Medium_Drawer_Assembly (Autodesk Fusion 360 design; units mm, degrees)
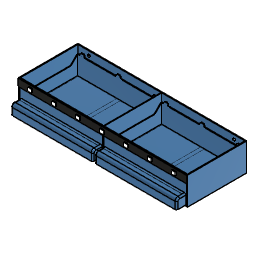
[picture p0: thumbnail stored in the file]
sketch "Bottom" plane through (0, 0, 0) normal (0, 0, 1) x axis (1, 0, 0)
  line L1 (232.6, 0) -> (0, 0)
  line L2 (232.6, 81.6) -> (232.6, 0)
  line L3 (0, 81.6) -> (232.6, 81.6)
  line L4 (0, 0) -> (0, 81.6)
  line L5 (231.4, 80.4) -> (1.2, 80.4)
  line L6 (231.4, 1.2) -> (231.4, 80.4)
  line L7 (1.2, 1.2) -> (231.4, 1.2)
  line L8 (1.2, 80.4) -> (1.2, 1.2)
  line L9 (3.2, 78.4) -> (3.2, 3.2)
  line L10 (34.2, 80.4) -> (33.4, 80.4)
  line L11 (33.4, 1.2) -> (34.2, 1.2)
  line L12 (67.2, 80.4) -> (66.4, 80.4)
  line L13 (66.4, 1.2) -> (67.2, 1.2)
  line L14 (100.2, 80.4) -> (99.4, 80.4)
  line L15 (99.4, 1.2032) -> (100.2, 1.2032)
  line L16 (133.2, 80.4) -> (132.4, 80.4)
  line L17 (132.4, 1.2) -> (133.2, 1.2)
  line L18 (166.2, 80.4) -> (165.4, 80.4)
  line L19 (165.4, 1.2) -> (166.2, 1.2)
  line L20 (199.2, 80.4) -> (198.4, 80.4)
  line L21 (198.4, 1.2) -> (199.2, 1.2)
  line L22 (229.4, 3.2) -> (229.4, 78.4)
  line L23 (232.2, 80.4) -> (231.4, 80.4)
  line L24 (231.4, 1.2) -> (232.2, 1.2)
  line L25 (115.9, 3.2) -> (115.9, 78.4)
  line L26 (116.7, 3.2) -> (116.7, 78.4)
  line L27 (116.7, 80.4) -> (116.7, 78.4)
  line L28 (115.9, 80.4) -> (115.9, 78.4)
  line L29 (116.7, 1.2) -> (116.7, 3.2)
  line L30 (115.9, 1.2) -> (115.9, 3.2)
  line L31 (113.9, 3.2) -> (113.9, 78.4)
  line L32 (113.9, 78.4) -> (3.2, 78.4)
  line L33 (3.2, 3.2) -> (113.9, 3.2)
  line L34 (118.7, 78.4) -> (229.4, 78.4)
  line L35 (118.7, 3.2) -> (118.7, 78.4)
  line L36 (118.7, 3.2) -> (229.4, 3.2)
  line L37 (56.2, 3.2) -> (56.2, 78.4)
  line L38 (61.2, 3.2) -> (61.2, 78.4)
  line L39 (171.7, 3.2) -> (171.7, 78.4)
  line L40 (176.7, 78.4) -> (176.7, 3.2)
  point P1 (0, 0)
  point P2 (0, 0)
  point P14 (34.2, 1.2)
  point P12 (33.4, 80.4)
  point P16 (66.4, 80.4)
  point P20 (99.4, 80.4)
  point P24 (132.4, 80.4)
  point P28 (165.4, 80.4)
  point P32 (198.4, 80.4)
  point P38 (231.4, 80.4)
  point P46 (116.7, 80.4)
  point P47 (115.9, 80.4)
  point P48 (116.7, 1.2)
  point P49 (115.9, 1.2)
  point P54 (56.2, 78.4)
  point P55 (56.2, 3.2)
  point P56 (61.2, 78.4)
  point P57 (61.2, 3.2)
  point P58 (171.7, 78.4)
  point P59 (171.7, 3.2)
  point P60 (176.7, 3.2)
  point P61 (176.7, 78.4)
  point P5 (0, 81.6)
  horizontal L1
  vertical L2
  horizontal L3
  vertical L4
  coincident P1 P2
  horizontal L5
  vertical L6
  horizontal L7
  vertical L8
  vertical L9
  horizontal L10
  coincident L7 P14
  coincident L5 P12
  horizontal L12
  horizontal L13
  coincident L5 P16
  horizontal L14
  horizontal L15
  coincident L5 P20
  horizontal L16
  horizontal L17
  coincident L5 P24
  horizontal L18
  horizontal L19
  coincident L5 P28
  horizontal L20
  horizontal L21
  coincident L5 P32
  vertical L22
  horizontal L23
  horizontal L24
  coincident L5 P38
  coincident L5 P46
  perpendicular L5 L27
  coincident L5 P47
  perpendicular L5 L28
  coincident L7 P48
  perpendicular L7 L29
  coincident L7 P49
  perpendicular L7 L30
  perpendicular L31 L32
  perpendicular L9 L33
  perpendicular L25 L34
  perpendicular L35 L36
  coincident L32 P54
  coincident L33 P55
  perpendicular L33 L37
  coincident L32 P56
  coincident L33 P57
  perpendicular L33 L38
  coincident L34 P58
  coincident L36 P59
  perpendicular L36 L39
  coincident L36 P60
  coincident L34 P61
  perpendicular L34 L40
  dimension "d1_3" distance L4 L8 = 1.2
  dimension "d2_3" distance L3 L5 = 1.2
  dimension "d3_3" distance L1 L7 = 1.2
  dimension "d4_3" distance L2 L6 = 1.2
  dimension "d5_3" distance L8 L9 = 2
  dimension "d8_1" distance P2 P5 = 81.6
  dimension "d52_2" distance L6 L22 = 2
  dimension "d173" distance L9 L25 = 112.7 (= "( ( 226.2 / 2 ) * 1 mm ) - 0.4 mm")
  dimension "d174" distance L22 L26 = 112.7 (= "( ( 226.2 / 2 ) * 1 mm ) - 0.4 mm")
  dimension "d175" distance L25 L26 = 0.8
  dimension "d190" distance L25 L31 = 2
  dimension "d191" distance L5 L32 = 2
  dimension "d192" distance L7 L33 = 2
  dimension "d193" distance L26 L35 = 2
  dimension "d194" distance L7 L36 = 2
  dimension "d195" distance L5 L34 = 2
  dimension "d203" distance L37 L38 = 5
  dimension "d204" distance L9 L37 = 53
  dimension "d206" distance L39 L40 = 5
  dimension "d207" distance L35 L39 = 53
extrude "Extrude2" new body sketch "Bottom" profile of L1 L2 L3 L4 L5 L6 L7 L8 L10 L11 L12 L13 L14 L16 L17 L18 L19 L20 L21 L25 L26 L27 L28 L29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 along normal blind 38.2 named "d57_2"
sketch "Front" plane through (0, 0, 0) normal (0, -1, 0) x axis (1, 0, 0)
  line L1 (232.6, 0) -> (0, 0)
  line L2 (232.6, 38.2) -> (232.6, 0)
  line L3 (0, 38.2) -> (232.6, 38.2)
  line L4 (0, 0) -> (0, 38.2)
  line L5 (33.4, 28.2) -> (1.2, 28.2)
  line L6 (1.2, 1.2) -> (33.4, 1.2)
  line L7 (1.2, 28.2) -> (1.2, 1.2)
  line L8 (1.2, 38.2) -> (1.2, 0)
  line L9 (231.4, 1.2) -> (231.4, 28.2)
  line L10 (231.4, 28.2) -> (33.4, 28.2)
  line L11 (33.4, 1.2) -> (231.4, 1.2)
  point P6 (1.2, 28.2)
  point P9 (1.2, 1.2)
  point P12 (231.4, 28.2)
  point P13 (231.4, 1.2)
  horizontal L5
  horizontal L6
  vertical L7
  collinear L7 L8
  vertical L9
  perpendicular L9 L10
  dimension "d80" distance P6 P9 = 27
  dimension "d83" distance L3 L5 = 10
  dimension "d91" distance P12 P13 = 27
  dimension "d294" distance L2 L9 = 1.2
sketch "Back" plane through (0, 80.4, 0) normal (0, -1, 0) x axis (1, 0, 0)
  line L1 (231.4, 38.2) -> (231.4, 0)
  line L2 (1.2, 38.2) -> (115.9, 38.2)
  line L3 (1.2, 0) -> (1.2, 38.2)
  line L4 (3.2, 7) -> (3.2, 23)
  line L5 (115.9, 38.2) -> (115.9, 0)
  line L6 (116.7, 0) -> (116.7, 38.2)
  line L7 (116.7, 38.2) -> (231.4, 38.2)
  line L8 (231.4, 0) -> (116.7, 0)
  line L9 (115.9, 0) -> (1.2, 0)
  line L10 (6.7355, 26.5355) -> (3.2, 23)
  line L11 (8.2, 23) -> (3.2, 23)
  line L12 (31.7355, 26.5355) -> (6.7355, 26.5355)
  line L13 (35.2711, 23) -> (31.7355, 26.5355)
  line L14 (36.7355, 26.5355) -> (31.7355, 26.5355)
  line L15 (35.2711, 7) -> (35.2711, 23)
  line L16 (31.7355, 3.4645) -> (35.2711, 7)
  line L17 (6.7355, 3.4645) -> (3.2, 7)
  line L18 (8.2, 7) -> (3.2, 7)
  line L19 (31.7355, 3.4645) -> (6.7355, 3.4645)
  line L20 (68.6066, 26.5355) -> (43.6066, 26.5355)
  line L21 (43.6066, 26.5355) -> (40.0711, 23)
  line L22 (40.0711, 7) -> (40.0711, 23)
  line L23 (43.6066, 3.4645) -> (40.0711, 7)
  line L24 (68.6066, 3.4645) -> (43.6066, 3.4645)
  line L25 (68.6066, 3.4645) -> (72.1421, 7)
  line L26 (72.1421, 7) -> (72.1421, 23)
  line L27 (72.1421, 23) -> (68.6066, 26.5355)
  line L28 (105.4777, 26.5355) -> (80.4777, 26.5355)
  line L29 (80.4777, 26.5355) -> (76.9421, 23)
  line L30 (76.9421, 7) -> (76.9421, 23)
  line L31 (80.4777, 3.4645) -> (76.9421, 7)
  line L32 (105.4777, 3.4645) -> (80.4777, 3.4645)
  line L33 (105.4777, 3.4645) -> (109.0132, 7)
  line L34 (109.0132, 7) -> (109.0132, 23)
  line L35 (109.0132, 23) -> (105.4777, 26.5355)
  line L36 (152.1223, 26.5355) -> (127.1223, 26.5355)
  line L37 (127.1223, 26.5355) -> (123.5868, 23)
  line L38 (123.5868, 7) -> (123.5868, 23)
  line L39 (127.1223, 3.4645) -> (123.5868, 7)
  line L40 (152.1223, 3.4645) -> (127.1223, 3.4645)
  line L41 (152.1223, 3.4645) -> (155.6579, 7)
  line L42 (155.6579, 7) -> (155.6579, 23)
  line L43 (155.6579, 23) -> (152.1223, 26.5355)
  line L44 (188.9934, 26.5355) -> (163.9934, 26.5355)
  line L45 (163.9934, 26.5355) -> (160.4579, 23)
  line L46 (160.4579, 7) -> (160.4579, 23)
  line L47 (163.9934, 3.4645) -> (160.4579, 7)
  line L48 (188.9934, 3.4645) -> (163.9934, 3.4645)
  line L49 (188.9934, 3.4645) -> (192.5289, 7)
  line L50 (192.5289, 7) -> (192.5289, 23)
  line L51 (192.5289, 23) -> (188.9934, 26.5355)
  line L52 (225.8645, 26.5355) -> (200.8645, 26.5355)
  line L53 (200.8645, 26.5355) -> (197.3289, 23)
  line L54 (197.3289, 7) -> (197.3289, 23)
  line L55 (200.8645, 3.4645) -> (197.3289, 7)
  line L56 (225.8645, 3.4645) -> (200.8645, 3.4645)
  line L57 (225.8645, 3.4645) -> (229.4, 7)
  line L58 (229.4, 7) -> (229.4, 23)
  line L59 (229.4, 23) -> (225.8645, 26.5355)
  line L60 (232.6, 38.2) -> (232.6, 0)
  point P5 (3.2, 7)
  point P6 (3.2, 23)
  point P12 (6.7355, 26.5355)
  point P14 (31.7355, 26.5355)
  point P15 (35.2711, 23)
  point P17 (35.2711, 7)
  point P18 (31.7355, 3.4645)
  point P19 (6.7355, 3.4645)
  point P23 (40.0711, 23)
  point P26 (40.0711, 7)
  point P21 (43.6066, 26.5355)
  point P28 (68.6066, 26.5355)
  point P27 (72.1421, 23)
  point P22 (68.6066, 3.4645)
  point P25 (72.1421, 7)
  point P24 (43.6066, 3.4645)
  point P31 (76.9421, 23)
  point P34 (76.9421, 7)
  point P29 (80.4777, 26.5355)
  point P36 (105.4777, 26.5355)
  point P35 (109.0132, 23)
  point P30 (105.4777, 3.4645)
  point P33 (109.0132, 7)
  point P32 (80.4777, 3.4645)
  point P39 (123.5868, 23)
  point P42 (123.5868, 7)
  point P37 (127.1223, 26.5355)
  point P44 (152.1223, 26.5355)
  point P43 (155.6579, 23)
  point P38 (152.1223, 3.4645)
  point P41 (155.6579, 7)
  point P40 (127.1223, 3.4645)
  point P47 (160.4579, 23)
  point P50 (160.4579, 7)
  point P45 (163.9934, 26.5355)
  point P52 (188.9934, 26.5355)
  point P51 (192.5289, 23)
  point P46 (188.9934, 3.4645)
  point P49 (192.5289, 7)
  point P48 (163.9934, 3.4645)
  point P55 (197.3289, 23)
  point P58 (197.3289, 7)
  point P53 (200.8645, 26.5355)
  point P60 (225.8645, 26.5355)
  point P59 (229.4, 23)
  point P54 (225.8645, 3.4645)
  point P57 (229.4, 7)
  point P56 (200.8645, 3.4645)
  parallel L3 L4
  horizontal L11
  horizontal L12
  horizontal L14
  vertical L15
  horizontal L18
  horizontal L20
  vertical L26
  horizontal L28
  vertical L34
  horizontal L36
  vertical L42
  horizontal L44
  vertical L50
  horizontal L52
  vertical L58
  dimension "d102" distance L3 L4 = 2
  dimension "d211" distance P5 P6 = 16
  dimension "d214" distance P5 L9 = 7
  dimension "d216" distance P6 P12 = 5
  dimension "d217" angle L10 L11 = 45
  dimension "d218" distance P12 P14 = 25
  dimension "d219" angle L13 L14 = 45
  dimension "d220" distance P14 P15 = 5
  dimension "d221" angle L15 L16 = 135
  dimension "d222" distance P17 P18 = 5
  dimension "d223" angle L17 L18 = 45
  dimension "d224" distance P5 P19 = 5
  dimension "d225" distance P23 P26 = 16
  dimension "d226" distance P21 P23 = 5
  dimension "d227" distance P21 P28 = 25
  dimension "d228" distance P27 P28 = 5
  dimension "d229" angle L25 L26 = 135
  dimension "d230" distance P22 P25 = 5
  dimension "d231" distance P24 P26 = 5
  dimension "d232" distance P31 P34 = 16
  dimension "d233" distance P29 P31 = 5
  dimension "d234" distance P29 P36 = 25
  dimension "d235" distance P35 P36 = 5
  dimension "d236" angle L33 L34 = 135
  dimension "d237" distance P30 P33 = 5
  dimension "d238" distance P32 P34 = 5
  dimension "d239" distance P39 P42 = 16
  dimension "d240" distance P37 P39 = 5
  dimension "d241" distance P37 P44 = 25
  dimension "d242" distance P43 P44 = 5
  dimension "d243" angle L41 L42 = 135
  dimension "d244" distance P38 P41 = 5
  dimension "d245" distance P40 P42 = 5
  dimension "d246" distance P47 P50 = 16
  dimension "d247" distance P45 P47 = 5
  dimension "d248" distance P45 P52 = 25
  dimension "d249" distance P51 P52 = 5
  dimension "d250" angle L49 L50 = 135
  dimension "d251" distance P46 P49 = 5
  dimension "d252" distance P48 P50 = 5
  dimension "d253" distance P55 P58 = 16
  dimension "d254" distance P53 P55 = 5
  dimension "d255" distance P53 P60 = 25
  dimension "d256" distance P59 P60 = 5
  dimension "d257" angle L57 L58 = 135
  dimension "d258" distance P54 P57 = 5
  dimension "d259" distance P56 P58 = 5
  dimension "d260" distance L15 L22 = 4.8
  dimension "d261" distance L26 L30 = 4.8
  dimension "d262" distance L50 L54 = 4.8
  dimension "d263" distance L42 L46 = 4.8
  dimension "d264" distance L36 L40 = 23.0711
  dimension "d265" distance L8 L40 = 3.4645
  dimension "d266" distance L38 L42 = 32.0711
  dimension "d267" distance L8 L48 = 3.4645
  dimension "d268" distance L58 L60 = 3.2
  dimension "d269" distance L6 L38 = 6.8868
  dimension "d270" angle L44 L45 = 135
  dimension "d272" angle L44 L51 = 135
  dimension "d273" distance L44 L48 = 23.0711
  dimension "d274" angle L52 L53 = 135
  dimension "d275" distance L52 L56 = 23.0711
  dimension "d279" angle L36 L37 = 135
  dimension "d280" distance L28 L32 = 23.0711
  dimension "d281" angle L28 L35 = 135
  dimension "d283" distance L30 L34 = 32.0711
  dimension "d284" distance L22 L26 = 32.0711
  dimension "d285" angle L20 L21 = 135
  dimension "d286" angle L20 L27 = 135
  dimension "d287" distance L20 L24 = 23.0711
  dimension "d288" angle L21 L22 = 135
  dimension "d290" distance L9 L24 = 3.4645
  dimension "d292" angle L16 L19 = 135
  dimension "d297" distance L9 L32 = 3.4645
  dimension "d298" distance L8 L56 = 3.4645
sketch "Mounting" plane through (0, 80.4, 0) normal (0, -1, 0) x axis (1, 0, 0)
  line L1 (231.4, 38.2) -> (231.4, 0)
  line L2 (1.2, 38.2) -> (115.9, 38.2)
  line L3 (1.2, 0) -> (1.2, 38.2)
  line L4 (115.9, 38.2) -> (115.9, 0)
  line L5 (116.7, 0) -> (116.7, 38.2)
  line L6 (116.7, 38.2) -> (231.4, 38.2)
  line L7 (231.4, 0) -> (116.7, 0)
  line L8 (115.9, 0) -> (1.2, 0)
  circle C1 centre (216.3, 32.2) radius 2
  circle C2 centre (16.3, 32.2) radius 2
  point P6 (16.3, 32.2)
  point P5 (216.3, 32.2)
  dimension "d165" diameter C1 = 4
  dimension "d166" diameter C2 = 4
  dimension "d167" distance L3 P6 = 15.1
  dimension "d168" distance L2 P6 = 6
  dimension "d169" distance L1 P5 = 15.1
  dimension "d170" distance L2 P5 = 6
extrude "Extrude9" cut sketch "Front" profile of L5 L6 L7 L8 L9 L10 L11 to an object
extrude "Extrude10" cut sketch "Back" profile of L4 L10 L12 L13 L15 L16 L17 L19 L20 L21 L22 L23 L24 L25 L26 L27 L28 L29 L30 L31 L32 L33 L34 L35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 against normal blind 1.2
extrude "Extrude11" cut sketch "Mounting" profile of C1 C2 against normal blind 1.2
extrude "Extrude12" add sketch "Bottom" profile of L5 L7 L8 L9 L10 L11 L12 L13 L14 L28 L30 to an object
extrude "Extrude13" add sketch "Bottom" profile of L5 L6 L7 L16 L17 L18 L19 L20 L21 L22 L26 L27 L29 L32 L33 L34 L35 L36 L37 L38 to an object
extrude "Extrude14" add of existing geometry to an object
extrude "Extrude15" add sketch "Bottom" profile of L34 L36 L39 L40 along normal blind 1.2
sketch "Sketch1" plane through (0, 0, 0) normal (0, 0, 1) x axis (1, 0, 0)
  line L1 (113.9, 0) -> (0, 0)
  line L2 (113.9, 80) -> (113.9, 0)
  line L3 (0, 80) -> (113.9, 80)
  line L4 (0, 0) -> (0, 80)
  point P1 (0, 0)
  point P2 (0, 0)
  point P3 (113.9, 0)
  point P4 (113.9, 80)
  horizontal L1
  vertical L2
  horizontal L3
  vertical L4
  coincident P1 P2
  dimension "d1_1" distance P2 P3 = 113.9 (= "114.7 mm - 0.8 mm")
  dimension "d2_1" distance P3 P4 = 80
extrude "Extrude1" new body sketch "Sketch1" along normal blind 26.2 named "d3_1"
shell "Shell1" innerThickness 0.8 named "d5_1"
work_plane "WorkPlane1" AlongDistance -18.4 named "d6_1"
sketch "Sketch3" plane through (0, 80, 0) normal (0, 1, 0) x axis (-1, 0, 0)
  line L1 (0, 0) -> (-113.9, 0)
  line L2 (0, 26.2) -> (0, 0)
  line L3 (-113.9, 26.2) -> (0, 26.2)
  line L4 (-113.9, 0) -> (-113.9, 26.2)
  line L5 (-56.95, 0) -> (-56.95, 26.2)
  line L6 (-109.65, 28.45) -> (-109.65, 27.45)
  line L7 (-105.4, 29.7) -> (-108.4, 29.7)
  line L8 (-104.15, 27.45) -> (-104.15, 28.45)
  line L9 (-102.9, 26.2) -> (-110.9, 26.2)
  line L10 (-8.5, 29.7) -> (-5.5, 29.7)
  line L11 (-4.25, 28.45) -> (-4.25, 27.45)
  line L12 (-11, 26.2) -> (-3, 26.2)
  line L13 (-9.75, 27.45) -> (-9.75, 28.45)
  line L14 (-55.25, 29.7) -> (-58.25, 29.7)
  line L15 (-59.5, 28.45) -> (-59.5, 27.45)
  line L16 (-52.75, 26.2) -> (-60.75, 26.2)
  line L17 (-54, 27.45) -> (-54, 28.45)
  arc A1 centre (-110.9, 27.45) radius 1.25 clockwise from (-109.65, 27.45) to (-110.9, 26.2)
  arc A2 centre (-108.4, 28.45) radius 1.25 clockwise from (-109.65, 28.45) to (-108.4, 29.7)
  arc A3 centre (-105.4, 28.45) radius 1.25 clockwise from (-105.4, 29.7) to (-104.15, 28.45)
  arc A4 centre (-102.9, 27.45) radius 1.25 clockwise from (-102.9, 26.2) to (-104.15, 27.45)
  arc A5 centre (-5.5, 28.45) radius 1.25 clockwise from (-5.5, 29.7) to (-4.25, 28.45)
  arc A6 centre (-11, 27.45) radius 1.25 clockwise from (-9.75, 27.45) to (-11, 26.2)
  arc A7 centre (-3, 27.45) radius 1.25 clockwise from (-3, 26.2) to (-4.25, 27.45)
  arc A8 centre (-8.5, 28.45) radius 1.25 clockwise from (-9.75, 28.45) to (-8.5, 29.7)
  arc A9 centre (-58.25, 28.45) radius 1.25 clockwise from (-59.5, 28.45) to (-58.25, 29.7)
  arc A10 centre (-60.75, 27.45) radius 1.25 clockwise from (-59.5, 27.45) to (-60.75, 26.2)
  arc A11 centre (-52.75, 27.45) radius 1.25 clockwise from (-52.75, 26.2) to (-54, 27.45)
  arc A12 centre (-55.25, 28.45) radius 1.25 clockwise from (-55.25, 29.7) to (-54, 28.45)
  point P10 (-56.95, 26.2)
  point P11 (-56.95, 0)
  point P20 (-106.9, 29.7)
  point P12 (-109.65, 27.45)
  point P27 (-4.25, 27.45)
  point P13 (-109.65, 28.45)
  point P21 (-4.25, 28.45)
  point P14 (-108.4, 29.7)
  point P28 (-5.5, 29.7)
  point P15 (-105.4, 29.7)
  point P26 (-8.5, 29.7)
  point P16 (-104.15, 28.45)
  point P23 (-9.75, 28.45)
  point P17 (-104.15, 27.45)
  point P22 (-9.75, 27.45)
  point P18 (-110.9, 26.2)
  point P30 (-3, 26.2)
  point P19 (-102.9, 26.2)
  point P29 (-11, 26.2)
  point P31 (-7, 29.7)
  point P44 (-60.75, 26.2)
  point P45 (-52.75, 26.2)
  point P36 (-58.25, 29.7)
  point P40 (-55.25, 29.7)
  midpoint L3 P10
  perpendicular L3 L5
  coincident L1 P11
  horizontal L7
  tangent L7 A2
  tangent L6 A2
  tangent L6 A1
  tangent L7 A3
  tangent L8 A3
  tangent L8 A4
  tangent L9 A4
  tangent L9 A1
  equal A1 A2
  equal A2 A3
  equal A3 A4
  collinear L3 L9
  vertical L8
  vertical L6
  midpoint L7 P20
  symmetric L5 P12 P27
  symmetric L5 P13 P21
  symmetric L5 P14 P28
  symmetric L5 P15 P26
  symmetric L5 P16 P23
  symmetric L5 P17 P22
  symmetric L5 P18 P30
  symmetric L5 P19 P29
  symmetric L5 P20 P31
  symmetric L5 A1 A7
  symmetric L5 A2 A5
  symmetric L5 A3 A8
  symmetric L5 A4 A6
  horizontal L14
  tangent L14 A9
  tangent A9 L15
  tangent L15 A10
  tangent L14 A12
  tangent L17 A12
  tangent A11 L17
  tangent A11 L16
  tangent A10 L16
  equal A9 A10
  equal A9 A12
  equal A11 A12
  vertical L17
  vertical L15
  dimension "d18_1" distance L4 P20 = 7
  dimension "d19_1" distance L7 L9 = 3.5
  dimension "d20_1" distance L6 L8 = 5.5
  dimension "d21_1" radius A1 = 1.25
  dimension "d62" distance L14 L16 = 3.5
  dimension "d63" distance L15 L17 = 5.5
  dimension "d64" radius A10 = 1.25
  dimension "d65" = 114.3
  dimension "d66" distance L8 L15 = 44.65
  dimension "d67" = 44.8
  dimension "d68" distance P44 P45 = 8
  dimension "d69" radius A11 = 1.25
  dimension "d70" distance P36 P40 = 3
  dimension "d71" radius A12 = 1.25
  dimension "d72" radius A10 = 1.25
  dimension "d73" radius A9 = 1.25
  dimension "d74" distance P10 L14 = 3.5
extrude "Extrude3" add sketch "Sketch3" profile of L3 A1 A2 A3 A4 L6 L7 L8 L9 A5 L10 A6 A7 L11 L12 A8 L13 L14 A9 L15 A10 A11 L16 L17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 against normal blind 0.8 named "d22_1"
sketch "Sketch4" plane through (113.9, 0, 0) normal (1, 0, 0) x axis (0, 1, 0)
  line L1 (80, 0) -> (0, 0)
  line L2 (80, 26.2) -> (80, 0)
  line L3 (0, 26.2) -> (80, 26.2)
  line L4 (0, 0) -> (0, 26.2)
  line L5 (10.1071, 17) -> (0.9071, 26.2)
  line L6 (7.8528, 26.2) -> (0.9071, 26.2)
  line L7 (69.7311, 17) -> (10.1071, 17)
  line L8 (78.9311, 26.2) -> (69.7311, 17)
  line L9 (0.9071, 26.2) -> (78.9311, 26.2)
  point P6 (0.9071, 26.2)
  point P10 (78.9311, 26.2)
  horizontal L6
  coincident L3 P6
  horizontal L7
  coincident L3 P10
  dimension "d24_1" angle L5 L6 = 45
  dimension "d25_1" angle L7 L8 = 135
  dimension "d26_1" distance L1 L7 = 17
extrude "Extrude4" cut sketch "Sketch4" profile of L3 L5 L7 L8 L9 to an object
extrude "Extrude5" add of existing geometry blind 0.4 named "d29_1"
sketch "Sketch5" plane through (0, 0, 0) normal (0, -1, 0) x axis (1, 0, 0)
  line L1 (113.9, 0) -> (0, 0)
  line L2 (113.9, 26.2) -> (113.9, 0)
  line L3 (0, 26.2) -> (113.9, 26.2)
  line L4 (0, 0) -> (0, 26.2)
  line L5 (113.4, 13.8) -> (0.5, 13.8)
  line L6 (113.4, 13) -> (113.4, 13.8)
  line L7 (0.5, 13) -> (113.4, 13)
  line L8 (0.5, 13.8) -> (0.5, 13)
  horizontal L5
  vertical L6
  horizontal L7
  vertical L8
  dimension "d31_1" distance L4 L8 = 0.5
  dimension "d32_1" distance L2 L6 = 0.5
  dimension "d33_1" distance L5 L7 = 0.8
  dimension "d34" distance L1 L7 = 13
extrude "Extrude6" add sketch "Sketch5" profile of L5 L6 L7 L8 along normal blind 13
sketch "Sketch6" plane through (0, 0, 13) normal (0, 0, -1) x axis (1, 0, 0)
  line L1 (113.4, 0) -> (0.5, 0)
  line L2 (113.4, 13) -> (113.4, 0)
  line L3 (0.5, 13) -> (113.4, 13)
  line L4 (0.5, 0) -> (0.5, 13)
  line L5 (31.3, 13) -> (0.5, 13)
  line L6 (0.5, 12.2) -> (31.3, 12.2)
  line L7 (0.5, 13) -> (0.5, 12.2)
  line L8 (113.4, 13) -> (31.3, 13)
  line L9 (113.4, 12.2) -> (31.3, 12.2)
  line L10 (113.4, 13) -> (113.4, 12.2)
  point P5 (0.5, 13)
  point P6 (0.5, 13)
  point P4 (113.4, 13)
  point P10 (113.4, 13)
  point P11 (113.4, 12.2)
  point P9 (0.5, 12.2)
  horizontal L5
  horizontal L6
  vertical L7
  coincident P5 P6
  coincident P4 P10
  coincident L2 P11
  perpendicular L2 L9
  dimension "d37" distance P6 P9 = 0.8
extrude "Extrude7" add sketch "Sketch6" profile of L2 L3 L4 L5 L6 L7 L8 L9 L10 along normal blind 13
sketch "Sketch8" plane through (0, 0, 13) normal (0, 0, -1) x axis (1, 0, 0)
  line L1 (0.5, 12.2) -> (113.4, 12.2)
  line L2 (0.5, 0) -> (0.5, 12.2)
  line L3 (113.4, 0) -> (0.5, 0)
  line L4 (113.4, 12.2) -> (113.4, 0)
  line L5 (0.5, 0) -> (1.3, 0)
  line L6 (0.5, 12.2) -> (0.5, 0)
  line L7 (1.3, 12.2) -> (0.5, 12.2)
  line L8 (1.3, 0) -> (1.3, 12.2)
  line L9 (112.6, 0) -> (113.4, 0)
  line L10 (112.6, 12.2) -> (112.6, 0)
  line L11 (113.4, 12.2) -> (112.6, 12.2)
  line L12 (113.4, 0) -> (113.4, 12.2)
  point P3 (0.5, 12.2)
  point P8 (0.5, 12.2)
  point P6 (1.3, 0)
  point P12 (112.6, 12.2)
  point P5 (113.4, 0)
  point P10 (113.4, 0)
  point P13 (113.4, 12.2)
  point P9 (1.3, 12.2)
  horizontal L5
  vertical L6
  horizontal L7
  vertical L8
  coincident P3 P8
  coincident L3 P6
  horizontal L9
  vertical L10
  horizontal L11
  vertical L12
  coincident L1 P12
  coincident P5 P10
  dimension "d45" distance P12 P13 = 0.8
  dimension "d46" distance P8 P9 = 0.8
extrude "Extrude9" add sketch "Sketch8" along normal blind 13
fillet "Fillet2" radius 4
chamfer "Chamfer1" distance 3
fillet "Fillet4" radius 2
fillet "Fillet5" radius 2
fillet "Fillet6" radius 2
sketch "Sketch1" plane through (0, 0, 0) normal (0, 0, 1) x axis (1, 0, 0)
  line L1 (113.9, 0) -> (0, 0)
  line L2 (113.9, 80) -> (113.9, 0)
  line L3 (0, 80) -> (113.9, 80)
  line L4 (0, 0) -> (0, 80)
  point P1 (0, 0)
  point P2 (0, 0)
  point P3 (113.9, 0)
  point P4 (113.9, 80)
  horizontal L1
  vertical L2
  horizontal L3
  vertical L4
  coincident P1 P2
  dimension "d1_2" distance P2 P3 = 113.9 (= "114.7 mm - 0.8 mm")
  dimension "d2_2" distance P3 P4 = 80
extrude "Extrude1" new body sketch "Sketch1" along normal blind 26.2 named "d3_2"
shell "Shell1" innerThickness 0.8 named "d5_2"
work_plane "WorkPlane1" AlongDistance -18.4 named "d6_2"
sketch "Sketch3" plane through (0, 80, 0) normal (0, 1, 0) x axis (-1, 0, 0)
  line L1 (0, 0) -> (-113.9, 0)
  line L2 (0, 26.2) -> (0, 0)
  line L3 (-113.9, 26.2) -> (0, 26.2)
  line L4 (-113.9, 0) -> (-113.9, 26.2)
  line L5 (-56.95, 0) -> (-56.95, 26.2)
  line L6 (-109.65, 28.45) -> (-109.65, 27.45)
  line L7 (-105.4, 29.7) -> (-108.4, 29.7)
  line L8 (-104.15, 27.45) -> (-104.15, 28.45)
  line L9 (-102.9, 26.2) -> (-110.9, 26.2)
  line L10 (-8.5, 29.7) -> (-5.5, 29.7)
  line L11 (-4.25, 28.45) -> (-4.25, 27.45)
  line L12 (-11, 26.2) -> (-3, 26.2)
  line L13 (-9.75, 27.45) -> (-9.75, 28.45)
  line L14 (-55.25, 29.7) -> (-58.25, 29.7)
  line L15 (-59.5, 28.45) -> (-59.5, 27.45)
  line L16 (-52.75, 26.2) -> (-60.75, 26.2)
  line L17 (-54, 27.45) -> (-54, 28.45)
  arc A1 centre (-110.9, 27.45) radius 1.25 clockwise from (-109.65, 27.45) to (-110.9, 26.2)
  arc A2 centre (-108.4, 28.45) radius 1.25 clockwise from (-109.65, 28.45) to (-108.4, 29.7)
  arc A3 centre (-105.4, 28.45) radius 1.25 clockwise from (-105.4, 29.7) to (-104.15, 28.45)
  arc A4 centre (-102.9, 27.45) radius 1.25 clockwise from (-102.9, 26.2) to (-104.15, 27.45)
  arc A5 centre (-5.5, 28.45) radius 1.25 clockwise from (-5.5, 29.7) to (-4.25, 28.45)
  arc A6 centre (-11, 27.45) radius 1.25 clockwise from (-9.75, 27.45) to (-11, 26.2)
  arc A7 centre (-3, 27.45) radius 1.25 clockwise from (-3, 26.2) to (-4.25, 27.45)
  arc A8 centre (-8.5, 28.45) radius 1.25 clockwise from (-9.75, 28.45) to (-8.5, 29.7)
  arc A9 centre (-58.25, 28.45) radius 1.25 clockwise from (-59.5, 28.45) to (-58.25, 29.7)
  arc A10 centre (-60.75, 27.45) radius 1.25 clockwise from (-59.5, 27.45) to (-60.75, 26.2)
  arc A11 centre (-52.75, 27.45) radius 1.25 clockwise from (-52.75, 26.2) to (-54, 27.45)
  arc A12 centre (-55.25, 28.45) radius 1.25 clockwise from (-55.25, 29.7) to (-54, 28.45)
  point P10 (-56.95, 26.2)
  point P11 (-56.95, 0)
  point P20 (-106.9, 29.7)
  point P12 (-109.65, 27.45)
  point P27 (-4.25, 27.45)
  point P13 (-109.65, 28.45)
  point P21 (-4.25, 28.45)
  point P14 (-108.4, 29.7)
  point P28 (-5.5, 29.7)
  point P15 (-105.4, 29.7)
  point P26 (-8.5, 29.7)
  point P16 (-104.15, 28.45)
  point P23 (-9.75, 28.45)
  point P17 (-104.15, 27.45)
  point P22 (-9.75, 27.45)
  point P18 (-110.9, 26.2)
  point P30 (-3, 26.2)
  point P19 (-102.9, 26.2)
  point P29 (-11, 26.2)
  point P31 (-7, 29.7)
  point P44 (-60.75, 26.2)
  point P45 (-52.75, 26.2)
  point P36 (-58.25, 29.7)
  point P40 (-55.25, 29.7)
  midpoint L3 P10
  perpendicular L3 L5
  coincident L1 P11
  horizontal L7
  tangent L7 A2
  tangent L6 A2
  tangent L6 A1
  tangent L7 A3
  tangent L8 A3
  tangent L8 A4
  tangent L9 A4
  tangent L9 A1
  equal A1 A2
  equal A2 A3
  equal A3 A4
  collinear L3 L9
  vertical L8
  vertical L6
  midpoint L7 P20
  symmetric L5 P12 P27
  symmetric L5 P13 P21
  symmetric L5 P14 P28
  symmetric L5 P15 P26
  symmetric L5 P16 P23
  symmetric L5 P17 P22
  symmetric L5 P18 P30
  symmetric L5 P19 P29
  symmetric L5 P20 P31
  symmetric L5 A1 A7
  symmetric L5 A2 A5
  symmetric L5 A3 A8
  symmetric L5 A4 A6
  horizontal L14
  tangent L14 A9
  tangent A9 L15
  tangent L15 A10
  tangent L14 A12
  tangent L17 A12
  tangent A11 L17
  tangent A11 L16
  tangent A10 L16
  equal A9 A10
  equal A9 A12
  equal A11 A12
  vertical L17
  vertical L15
  dimension "d18_2" distance L4 P20 = 7
  dimension "d19_2" distance L7 L9 = 3.5
  dimension "d20_2" distance L6 L8 = 5.5
  dimension "d21_2" radius A1 = 1.25
  dimension "d62_1" distance L14 L16 = 3.5
  dimension "d63_1" distance L15 L17 = 5.5
  dimension "d64_1" radius A10 = 1.25
  dimension "d65_1" = 114.3
  dimension "d66_1" distance L8 L15 = 44.65
  dimension "d67_1" = 44.8
  dimension "d68_1" distance P44 P45 = 8
  dimension "d69_1" radius A11 = 1.25
  dimension "d70_1" distance P36 P40 = 3
  dimension "d71_1" radius A12 = 1.25
  dimension "d72_1" radius A10 = 1.25
  dimension "d73_1" radius A9 = 1.25
  dimension "d74_1" distance P10 L14 = 3.5
extrude "Extrude3" add sketch "Sketch3" profile of L3 A1 A2 A3 A4 L6 L7 L8 L9 A5 L10 A6 A7 L11 L12 A8 L13 L14 A9 L15 A10 A11 L16 L17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 against normal blind 0.8 named "d22_2"
sketch "Sketch4" plane through (113.9, 0, 0) normal (1, 0, 0) x axis (0, 1, 0)
  line L1 (80, 0) -> (0, 0)
  line L2 (80, 26.2) -> (80, 0)
  line L3 (0, 26.2) -> (80, 26.2)
  line L4 (0, 0) -> (0, 26.2)
  line L5 (10.1071, 17) -> (0.9071, 26.2)
  line L6 (7.8528, 26.2) -> (0.9071, 26.2)
  line L7 (69.7311, 17) -> (10.1071, 17)
  line L8 (78.9311, 26.2) -> (69.7311, 17)
  line L9 (0.9071, 26.2) -> (78.9311, 26.2)
  point P6 (0.9071, 26.2)
  point P10 (78.9311, 26.2)
  horizontal L6
  coincident L3 P6
  horizontal L7
  coincident L3 P10
  dimension "d24_2" angle L5 L6 = 45
  dimension "d25_2" angle L7 L8 = 135
  dimension "d26_2" distance L1 L7 = 17
extrude "Extrude4" cut sketch "Sketch4" profile of L3 L5 L7 L8 L9 to an object
extrude "Extrude5" add of existing geometry blind 0.4 named "d29_2"
sketch "Sketch5" plane through (0, 0, 0) normal (0, -1, 0) x axis (1, 0, 0)
  line L1 (113.9, 0) -> (0, 0)
  line L2 (113.9, 26.2) -> (113.9, 0)
  line L3 (0, 26.2) -> (113.9, 26.2)
  line L4 (0, 0) -> (0, 26.2)
  line L5 (113.4, 13.8) -> (0.5, 13.8)
  line L6 (113.4, 13) -> (113.4, 13.8)
  line L7 (0.5, 13) -> (113.4, 13)
  line L8 (0.5, 13.8) -> (0.5, 13)
  horizontal L5
  vertical L6
  horizontal L7
  vertical L8
  dimension "d31_2" distance L4 L8 = 0.5
  dimension "d32_2" distance L2 L6 = 0.5
  dimension "d33_2" distance L5 L7 = 0.8
  dimension "d34_1" distance L1 L7 = 13
extrude "Extrude6" add sketch "Sketch5" profile of L5 L6 L7 L8 along normal blind 13 named "d35_1"
sketch "Sketch6" plane through (0, 0, 13) normal (0, 0, -1) x axis (1, 0, 0)
  line L1 (113.4, 0) -> (0.5, 0)
  line L2 (113.4, 13) -> (113.4, 0)
  line L3 (0.5, 13) -> (113.4, 13)
  line L4 (0.5, 0) -> (0.5, 13)
  line L5 (31.3, 13) -> (0.5, 13)
  line L6 (0.5, 12.2) -> (31.3, 12.2)
  line L7 (0.5, 13) -> (0.5, 12.2)
  line L8 (113.4, 13) -> (31.3, 13)
  line L9 (113.4, 12.2) -> (31.3, 12.2)
  line L10 (113.4, 13) -> (113.4, 12.2)
  point P5 (0.5, 13)
  point P6 (0.5, 13)
  point P4 (113.4, 13)
  point P10 (113.4, 13)
  point P11 (113.4, 12.2)
  point P9 (0.5, 12.2)
  horizontal L5
  horizontal L6
  vertical L7
  coincident P5 P6
  coincident P4 P10
  coincident L2 P11
  perpendicular L2 L9
  dimension "d37_1" distance P6 P9 = 0.8
extrude "Extrude7" add sketch "Sketch6" profile of L2 L3 L4 L5 L6 L7 L8 L9 L10 along normal blind 13 named "d38_1"
sketch "Sketch8" plane through (0, 0, 13) normal (0, 0, -1) x axis (1, 0, 0)
  line L1 (0.5, 12.2) -> (113.4, 12.2)
  line L2 (0.5, 0) -> (0.5, 12.2)
  line L3 (113.4, 0) -> (0.5, 0)
  line L4 (113.4, 12.2) -> (113.4, 0)
  line L5 (0.5, 0) -> (1.3, 0)
  line L6 (0.5, 12.2) -> (0.5, 0)
  line L7 (1.3, 12.2) -> (0.5, 12.2)
  line L8 (1.3, 0) -> (1.3, 12.2)
  line L9 (112.6, 0) -> (113.4, 0)
  line L10 (112.6, 12.2) -> (112.6, 0)
  line L11 (113.4, 12.2) -> (112.6, 12.2)
  line L12 (113.4, 0) -> (113.4, 12.2)
  point P3 (0.5, 12.2)
  point P8 (0.5, 12.2)
  point P6 (1.3, 0)
  point P12 (112.6, 12.2)
  point P5 (113.4, 0)
  point P10 (113.4, 0)
  point P13 (113.4, 12.2)
  point P9 (1.3, 12.2)
  horizontal L5
  vertical L6
  horizontal L7
  vertical L8
  coincident P3 P8
  coincident L3 P6
  horizontal L9
  vertical L10
  horizontal L11
  vertical L12
  coincident L1 P12
  coincident P5 P10
  dimension "d45_1" distance P12 P13 = 0.8
  dimension "d46_1" distance P8 P9 = 0.8
extrude "Extrude9" add sketch "Sketch8" along normal blind 13 named "d47_1"
fillet "Fillet2" radius 4 named "d49_1"
chamfer "Chamfer1" distance 3 named "d50_1"
fillet "Fillet4" radius 2 named "d52_1"
fillet "Fillet5" radius 2 named "d56_1"
fillet "Fillet6" radius 2 named "d57_1"
sketch "Sketch1" plane through (0, 0, 0) normal (0, -1, 0) x axis (1, 0, 0)
  line L1 (1.2, 1.2) -> (115.9, 1.2)
  line L2 (1.2, 28.2) -> (1.2, 1.2)
  line L3 (115.9, 28.2) -> (1.2, 28.2)
  line L4 (115.9, 1.2) -> (115.9, 28.2)
  line L5 (116.7, 28.2) -> (116.7, 1.2)
  line L6 (231.4, 28.2) -> (116.7, 28.2)
  line L7 (231.4, 1.2) -> (231.4, 28.2)
  line L8 (116.7, 1.2) -> (231.4, 1.2)
  line L9 (232.6, 0) -> (0, 0)
  line L10 (232.6, 38.2) -> (232.6, 0)
  line L11 (0, 38.2) -> (232.6, 38.2)
  line L12 (0, 0) -> (0, 38.2)
  line L13 (232.6, 38.2) -> (0, 38.2)
  line L14 (232.6, 28.2) -> (232.6, 38.2)
  line L15 (0, 28.2) -> (232.6, 28.2)
  line L16 (0, 38.2) -> (0, 28.2)
  point P16 (232.6, 28.2)
  point P13 (0, 38.2)
  point P14 (0, 38.2)
  point P15 (232.6, 38.2)
  horizontal L13
  vertical L14
  horizontal L15
  vertical L16
  coincident L10 P16
  coincident P13 P14
  dimension "d1" distance P15 P16 = 10
extrude "Extrude1" new body sketch "Sketch1" profile of L3 L6 L10 L11 L12 L13 L14 L15 L16 along normal blind 1
sketch "Sketch2" plane through (0, -1, 0) normal (0, -1, 0) x axis (1, 0, 0)
  line L1 (232.6, 28.2) -> (0, 28.2)
  line L2 (232.6, 38.2) -> (232.6, 28.2)
  line L3 (0, 38.2) -> (232.6, 38.2)
  line L4 (0, 28.2) -> (0, 38.2)
  line L5 (20, 35.7) -> (15, 35.7)
  line L6 (20, 30.7) -> (20, 35.7)
  line L7 (15, 30.7) -> (20, 30.7)
  line L8 (15, 35.7) -> (15, 30.7)
  line L9 (53, 35.7) -> (48, 35.7)
  line L10 (53, 30.7) -> (53, 35.7)
  line L11 (48, 30.7) -> (53, 30.7)
  line L12 (48, 35.7) -> (48, 30.7)
  line L13 (86, 35.7) -> (81, 35.7)
  line L14 (86, 30.7) -> (86, 35.7)
  line L15 (81, 30.7) -> (86, 30.7)
  line L16 (81, 35.7) -> (81, 30.7)
  line L17 (119, 35.7) -> (114, 35.7)
  line L18 (119, 30.7) -> (119, 35.7)
  line L19 (114, 30.7) -> (119, 30.7)
  line L20 (114, 35.7) -> (114, 30.7)
  line L21 (152, 35.7) -> (147, 35.7)
  line L22 (152, 30.7) -> (152, 35.7)
  line L23 (147, 30.7) -> (152, 30.7)
  line L24 (147, 35.7) -> (147, 30.7)
  line L25 (185, 35.7) -> (180, 35.7)
  line L26 (185, 30.7) -> (185, 35.7)
  line L27 (180, 30.7) -> (185, 30.7)
  line L28 (180, 35.7) -> (180, 30.7)
  line L29 (218, 35.7) -> (213, 35.7)
  line L30 (218, 30.7) -> (218, 35.7)
  line L31 (213, 30.7) -> (218, 30.7)
  line L32 (213, 35.7) -> (213, 30.7)
  point P6 (15, 35.7)
  point P7 (20, 35.7)
  point P10 (48, 35.7)
  point P11 (53, 35.7)
  point P14 (81, 35.7)
  point P15 (86, 35.7)
  point P18 (114, 35.7)
  point P19 (119, 35.7)
  point P22 (147, 35.7)
  point P23 (152, 35.7)
  point P26 (180, 35.7)
  point P27 (185, 35.7)
  point P8 (20, 30.7)
  point P12 (53, 30.7)
  point P16 (86, 30.7)
  point P21 (114, 30.7)
  point P24 (152, 30.7)
  point P28 (185, 30.7)
  point P30 (213, 35.7)
  point P31 (218, 35.7)
  point P32 (218, 30.7)
  horizontal L5
  vertical L6
  horizontal L7
  vertical L8
  horizontal L9
  vertical L10
  horizontal L11
  vertical L12
  horizontal L13
  vertical L14
  horizontal L15
  vertical L16
  horizontal L17
  vertical L18
  horizontal L19
  vertical L20
  horizontal L21
  vertical L22
  horizontal L23
  vertical L24
  horizontal L25
  vertical L26
  horizontal L27
  vertical L28
  horizontal L29
  vertical L30
  horizontal L31
  vertical L32
  dimension "d4" distance P6 P7 = 5
  dimension "d5" distance P10 P11 = 5
  dimension "d6" distance P14 P15 = 5
  dimension "d7" distance P18 P19 = 5
  dimension "d8" distance P22 P23 = 5
  dimension "d9" distance P26 P27 = 5
  dimension "d10" distance L6 L12 = 28
  dimension "d11" distance P7 P8 = 5
  dimension "d12" distance P11 P12 = 5
  dimension "d13" distance P15 P16 = 5
  dimension "d14" distance L10 L16 = 28
  dimension "d15" distance L4 L8 = 15
  dimension "d16" distance L14 L20 = 28
  dimension "d17" distance L3 L13 = 2.5
  dimension "d18" distance L3 L17 = 2.5
  dimension "d19" distance L3 L9 = 2.5
  dimension "d20" distance L3 L5 = 2.5
  dimension "d21" distance L3 L21 = 2.5
  dimension "d22" distance P18 P21 = 5
  dimension "d23" distance P23 P24 = 5
  dimension "d24" distance L18 L24 = 28
  dimension "d25" distance P27 P28 = 5
  dimension "d26" distance L3 L25 = 2.5
  dimension "d27" distance L22 L28 = 28
  dimension "d28" distance P30 P31 = 5
  dimension "d29" distance P31 P32 = 5
  dimension "d30" distance L3 L29 = 2.5
  dimension "d31" distance L26 L32 = 28
extrude "Extrude3" add sketch "Sketch2" profile of L5 L6 L7 L8 L9 L10 L11 L12 L13 L14 L15 L16 L17 L18 L19 L20 L21 L22 L23 L24 L25 L26 L27 L28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 along normal blind 1.5
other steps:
create_component "CreateComponent1"
create_component "CreateComponent2"
create_component "CreateComponent3"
